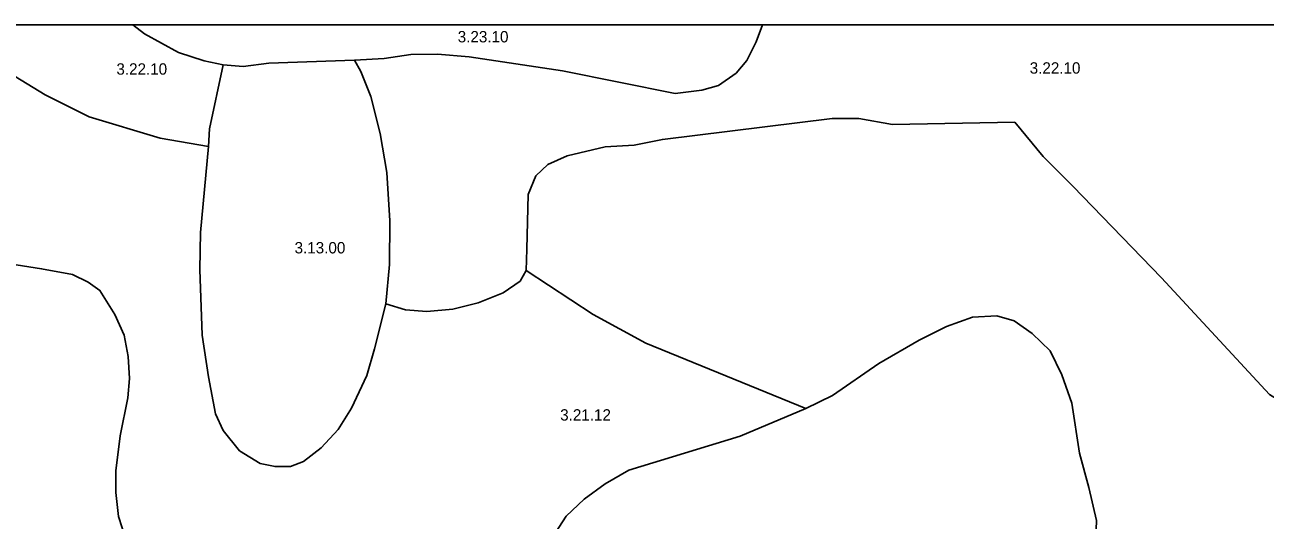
# Model space of a CAD drawing. Extents: x -662500 to -655523, y -1056000 to -1049993.
# Drawn here: x -661595 to -660777, y -1050327 to -1050000 of the extents above; entities that cross this region are included whole.
import ezdxf

# ---------------------------------------------------------------- set-up
doc = ezdxf.new("R2010")
doc.units = 0
doc.layers.add('Vrstva 24', color=7, linetype='Continuous')

msp = doc.modelspace()

# ---------------------------------------------------------------- linework, layer by layer
at = {"layer": 'Vrstva 24'}
for points in [[(-661645.56, -1050000.43), (-661634.69, -1050011.99), (-661618.17, -1050023.83), (-661581.27, -1050046.14), (-661552.22, -1050060.73), (-661505.41, -1050074.77), (-661473.61, -1050080.28)], [(-661639.64, -1050000), (-661523.54, -1050000)], [(-661523.54, -1050000), (-661108.33, -1050000)], [(-661523.54, -1050000), (-661515.87, -1050005.94), (-661493.3, -1050018.33), (-661476.5, -1050023.83), (-661463.83, -1050026.31)], [(-661377.37, -1050023.28), (-661357.82, -1050022.18), (-661340.2, -1050019.7), (-661322.58, -1050019.43), (-661301.65, -1050021.08), (-661240.11, -1050030.44), (-661165.77, -1050045.31), (-661148.29, -1050043.11), (-661137.27, -1050040.08), (-661125.71, -1050031.82), (-661118.55, -1050023.56), (-661112.49, -1050011.17), (-661108.33, -1050000)], [(-661108.33, -1050000), (-660703.41, -1050000)], [(-661463.83, -1050026.31), (-661450.62, -1050027.41), (-661433.82, -1050025.21), (-661377.37, -1050023.28)], [(-661377.37, -1050023.28), (-661373.24, -1050030.72), (-661366.5, -1050047.24), (-661360.44, -1050071.74), (-661356.03, -1050097.35), (-661354.11, -1050129.29), (-661354.24, -1050158.2), (-661356.72, -1050184.09)], [(-661473.61, -1050080.28), (-661472.92, -1050068.72), (-661463.83, -1050026.31)], [(-660664.18, -1050275.51), (-660700.77, -1050253.53), (-660750.63, -1050253.21), (-660760.82, -1050252.11), (-660774.04, -1050243.85), (-660845.22, -1050167.02), (-660903.59, -1050106.45), (-660923.28, -1050086.9), (-660942, -1050064.32), (-661022.68, -1050065.7), (-661044.71, -1050061.84), (-661062.33, -1050061.84), (-661174.26, -1050075.61), (-661192.98, -1050079.46), (-661211.98, -1050080.56), (-661237.17, -1050086.35), (-661249.84, -1050092.13), (-661257.82, -1050099.56), (-661262.78, -1050111.95), (-661263.61, -1050148.02), (-661264.16, -1050162.07)], [(-661356.72, -1050184.09), (-661364.16, -1050213.82), (-661369.11, -1050231.45), (-661379.3, -1050252.92), (-661388.11, -1050266.97), (-661399.4, -1050279.08), (-661410.97, -1050288.17), (-661419.5, -1050291.47), (-661429.69, -1050291.47), (-661439.6, -1050289.54), (-661453.09, -1050281.01), (-661463.83, -1050267.79), (-661469.06, -1050256.78), (-661473.61, -1050232.27), (-661477.74, -1050204.74), (-661479.39, -1050161.51), (-661478.84, -1050137), (-661473.61, -1050080.28)], [(-661527.99, -1050339.47), (-661532.94, -1050324.51), (-661534.6, -1050308.54), (-661534.6, -1050294.22), (-661531.84, -1050271.1), (-661526.75, -1050246.04), (-661525.65, -1050233.37), (-661526.47, -1050218.78), (-661529.23, -1050204.74), (-661535.29, -1050191.25), (-661545.2, -1050175.27), (-661552.91, -1050169.77), (-661563.23, -1050164.81), (-661583.61, -1050160.96), (-661616.1, -1050156)], [(-661356.72, -1050184.09), (-661343.64, -1050188.14), (-661329.6, -1050189.24), (-661312.52, -1050187.59), (-661295.73, -1050183.46), (-661279.21, -1050176.85), (-661268.19, -1050169.14), (-661264.16, -1050162.07)], [(-661264.16, -1050162.07), (-661219.96, -1050191.25), (-661185.27, -1050209.98), (-661079.81, -1050253.21)], [(-661079.81, -1050253.21), (-661062.19, -1050244.67), (-661031.49, -1050223.47), (-661005.06, -1050208.05), (-660986.88, -1050198.96), (-660969.81, -1050192.91), (-660953.84, -1050192.08), (-660942.28, -1050195.38), (-660930.44, -1050203.64), (-660918.6, -1050215.21), (-660910.89, -1050230.9), (-660904.28, -1050249.63), (-660899.18, -1050282.67), (-660893.13, -1050305.25), (-660888.17, -1050327), (-660888.72, -1050344.9), (-660892.58, -1050361.97), (-660897.67, -1050375.19), (-660907.31, -1050386.75)], [(-661079.81, -1050253.21), (-661123.04, -1050271.38), (-661196.42, -1050293.96), (-661212.12, -1050302.77), (-661225.88, -1050312.96), (-661237.72, -1050324.25), (-661247.36, -1050339.12), (-661256.17, -1050360.59), (-661258.51, -1050377.94)]]:
    msp.add_lwpolyline(points, dxfattribs=at)

# ---------------------------------------------------------------- texts
for s, p in [('3.23.10', (-661309.25, -1050011.61)), ('3.22.10', (-661534.32, -1050032.91)), ('3.22.10', (-660932.11, -1050032.23)), ('3.13.00', (-661416.82, -1050150.84)), ('3.21.12', (-661241.7, -1050261.14))]:
    msp.add_text(s, height=7.5, dxfattribs=at).set_placement(p)

doc.saveas('drawing.dxf')
